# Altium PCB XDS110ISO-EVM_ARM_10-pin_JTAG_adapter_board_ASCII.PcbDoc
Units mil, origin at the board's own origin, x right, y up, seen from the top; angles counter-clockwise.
Board outline 1100 x 500 mil, 2 copper layers (Top Signal, Bottom Signal), stack 58.8 mil thick; 2 components, 6 nets, 25 pads, 15 vias.
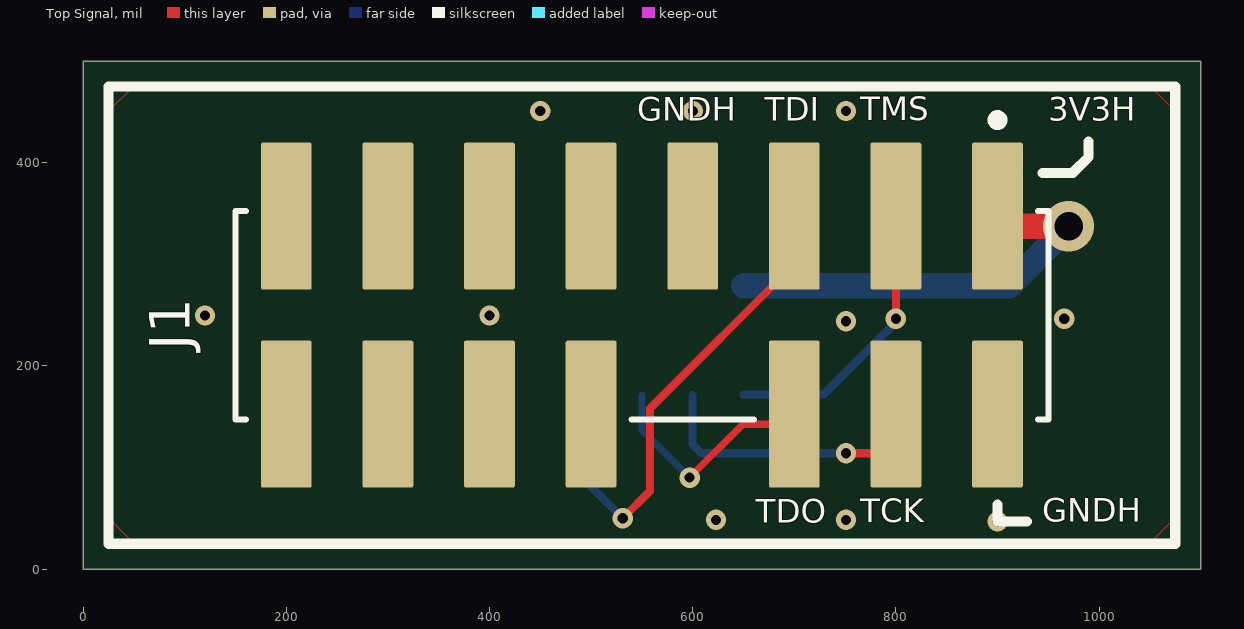
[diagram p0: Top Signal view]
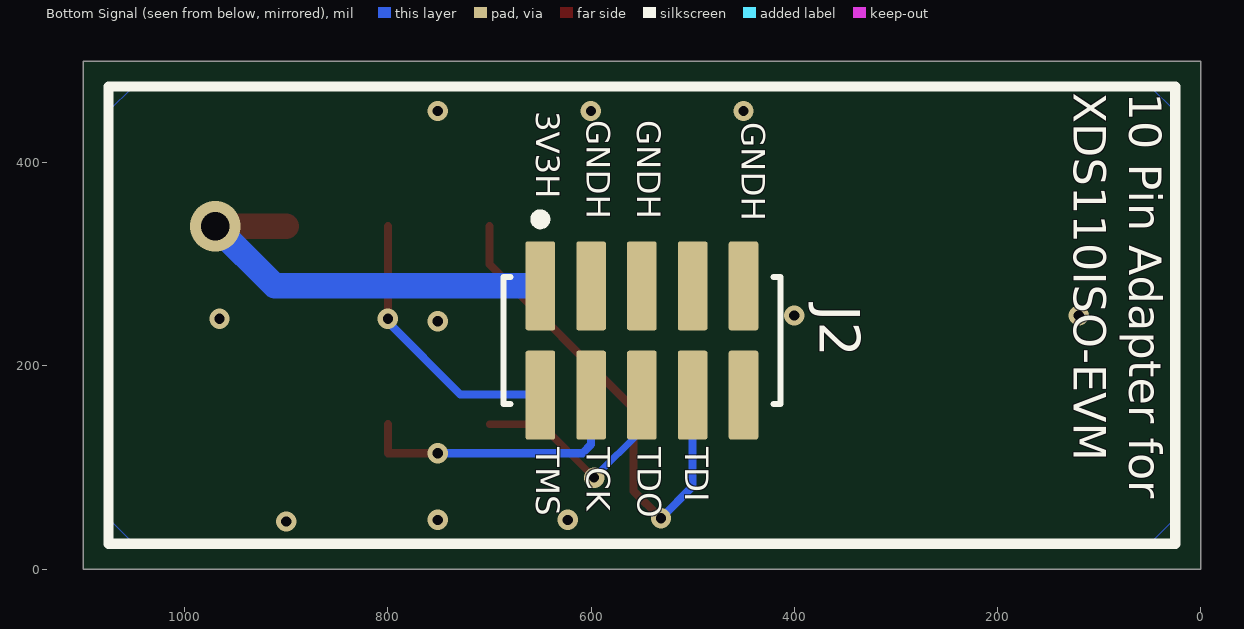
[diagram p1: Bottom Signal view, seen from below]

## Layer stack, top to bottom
Top Solder: solder mask 0.4, Solder Resist, Dk 3.5
Top Signal: signal copper 1.4
Dielectric 1: prepreg 8, FR-4, Dk 4.2
Dielectric 2: core 40, FR-4, Dk 4.2
Dielectric 3: prepreg 8, FR-4, Dk 4.2
Bottom Signal: signal copper 1.4
Bottom Solder: solder mask 0.4, Solder Resist, Dk 3.5

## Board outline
0,0 0,500 1100,500 1100,0

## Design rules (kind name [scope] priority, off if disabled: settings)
AcuteAngle [All] p0: scope1count=1 scope1_0_kind=Board scope1_0_value=Board scope2count=1 scope2_0_kind=Board scope2_0_value=Board commentlength=0 minimum=4.50000000000000E+0001
AcuteAngle [All] p1: minimum=4.50000000000000E+0001 checktracksonly=TRUE
AssemblyTestPointUsage [All] p0: scope1count=1 scope1_0_kind=Board scope1_0_value=Board scope2count=1 scope2_0_kind=Board scope2_0_value=Board commentlength=0
AssemblyTestPointUsage [All] p1: valid=2
AssemblyTestpoint [All] p0: scope1count=1 scope1_0_kind=Board scope1_0_value=Board scope2count=1 scope2_0_kind=Board scope2_0_value=Board commentlength=0
BoardOutlineClearance BoardOutlineClearance_USB101 [All] p0: scope1count=1 scope1_0_kind=Component scope1_0_value=USB101 scope2count=1 scope2_0_kind=Board scope2_0_value=Board commentlength=0 gap=0
BoardOutlineClearance [All] p0 off: scope1count=1 scope1_0_kind=Board scope1_0_value=Board scope2count=1 scope2_0_kind=Board scope2_0_value=Board commentlength=172 gap=10 // Protel DXP Scope 1 Expression Was: OnCopper and Not InComponentClass('Logo') and not InComponentClass('FiducialMark') and not InRegion(1000,500,4000,800) and not InPoly
BoardOutlineClearance BoardOutlineClearance_Poly [All] p0 off: scope1count=1 scope1_0_kind=Board scope1_0_value=Board scope2count=1 scope2_0_kind=Board scope2_0_value=Board commentlength=58 gap=25 // Protel DXP Scope 1 Expression Was: OnCopper and IsPoly
BoardOutlineClearance BoardOutlineClearance_MountingHoles [All] p0 off: scope1count=1 scope1_0_kind=Board scope1_0_value=Board scope2count=1 scope2_0_kind=Board scope2_0_value=Board commentlength=86 gap=40 // Protel DXP Scope 1 Expression Was: OnCopper and InComponentClass('Mounting Holes')
BoardOutlineClearance BoardOutlineClearance_MountingHoles [OnCopper and InComponentClass('Mounting Holes')] p1: gap=40 ignorepadtopadclearanceinfootprint=FALSE
BoardOutlineClearance BoardOutlineClearance_Poly [OnCopper and IsPoly] p2: gap=25 ignorepadtopadclearanceinfootprint=FALSE
BoardOutlineClearance BoardOutlineClearance_USB101 [InComponent('USB101')] p3: gap=0 ignorepadtopadclearanceinfootprint=FALSE
BoardOutlineClearance [OnCopper and Not InComponentClass('Logo') and not InComponentClass('FiducialMark') and not InRegion(1000,500,4000,800) and not InPoly] p4: gap=10 ignorepadtopadclearanceinfootprint=FALSE
Clearance Clearance_PTH [All] p0 off: scope1count=1 scope1_0_kind=Board scope1_0_value=Board scope2count=1 scope2_0_kind=Board scope2_0_value=Board commentlength=56 gap=7 // Protel DXP Scope 1 Expression Was: HoleDiameter > 10
Clearance Clearance_NPTH [All] p0 off: scope1count=1 scope1_0_kind=Board scope1_0_value=Board scope2count=1 scope2_0_kind=Board scope2_0_value=Board commentlength=56 gap=15 // Protel DXP Scope 1 Expression Was: HoleDiameter = 39
Clearance Clearance_FiducialMark [All] p0: scope1count=1 scope1_0_kind=ComponentClass scope1_0_value=FiducialMark scope2count=1 scope2_0_kind=ComponentClass scope2_0_value=FiducialMark commentlength=0 gap=0
Clearance Clearance_Boardedge [All] p0 off: scope1count=1 scope1_0_kind=Board scope1_0_value=Board scope2count=1 scope2_0_kind=Board scope2_0_value=Board commentlength=48 gap=11.8 // Protel DXP Scope 2 Expression Was: IsKeepOut
Clearance [All] p0: scope1count=1 scope1_0_kind=Board scope1_0_value=Board scope2count=1 scope2_0_kind=Board scope2_0_value=Board commentlength=0 gap=6
Clearance Clearance_NPTH [HoleDiameter = 39] p1: gap=15 ignorepadtopadclearanceinfootprint=FALSE
Clearance Clearance_PTH [HoleDiameter > 10] p2: gap=7 ignorepadtopadclearanceinfootprint=FALSE
Clearance Clearance_FiducialMark [InComponentClass('FiducialMark') vs InComponentClass('FiducialMark')] p3: gap=0 ignorepadtopadclearanceinfootprint=FALSE
Clearance Clearance_Boardedge [All vs IsKeepOut] p4: gap=11.8 ignorepadtopadclearanceinfootprint=FALSE
Clearance [All] p5: gap=6 ignorepadtopadclearanceinfootprint=FALSE
ComponentClearance ComponentClearance_THtoTH [All] p0 off: scope1count=1 scope1_0_kind=Board scope1_0_value=Board scope2count=1 scope2_0_kind=Board scope2_0_value=Board commentlength=54 gap=20 collisioncheckmode=3 // Protel DXP Scope 2 Expression Was: IsThruComponent
ComponentClearance ComponentClearance_THtoSMT [All] p0 off: scope1count=1 scope1_0_kind=Board scope1_0_value=Board scope2count=1 scope2_0_kind=Board scope2_0_value=Board commentlength=53 gap=10 collisioncheckmode=3 // Protel DXP Scope 2 Expression Was: IsSMTComponent
ComponentClearance ComponentClearance_SmallPassives [All] p0 off: scope1count=1 scope1_0_kind=Board scope1_0_value=Board scope2count=1 scope2_0_kind=Board scope2_0_value=Board commentlength=508 gap=10 collisioncheckmode=3 // Protel DXP Scope 2 Expression Was: HasFootprint('0201*') or HasFootprint('0402*') or HasFootprint('0508') or HasFootprint('0603*') or HasFootprint('0612') or HasFootprint('0805*') or HasFootprint('0815*') or HasFootprint('0830*') or HasFootprint('1206*') or HasFootprint('1210*') or HasFootprint('1808*') or HasFootprint('1812*') or HasFootprint('1825*') or HasFootprint('2010*') or HasFootprint('2220*') or HasFootprint('2225*') or HasFootprint('2512*') or HasFootprint('2728*') or HasFootprint('3518*')
ComponentClearance ComponentClearance_MountingHoles [All] p0 off: scope1count=1 scope1_0_kind=ComponentClass scope1_0_value="Mounting Holes" scope2count=1 scope2_0_kind=Board scope2_0_value=Board commentlength=0 gap=250 collisioncheckmode=3
ComponentClearance ComponentClearance_ScrewToNut [All] p0 off: scope1count=1 scope1_0_kind=Board scope1_0_value=Board scope2count=1 scope2_0_kind=Board scope2_0_value=Board commentlength=71 gap=3.94 collisioncheckmode=3 // Protel DXP Scope 2 Expression Was: (HasFootprint('Keystone_1902C'))
ComponentClearance ComponentClearance_Logo [All] p0: scope1count=1 scope1_0_kind=ComponentClass scope1_0_value=Logo scope2count=1 scope2_0_kind=Board scope2_0_value=Board commentlength=0 gap=0 collisioncheckmode=3
ComponentClearance ComponentClearance_Shunt [All] p0: scope1count=1 scope1_0_kind=ComponentClass scope1_0_value=Header scope2count=1 scope2_0_kind=ComponentClass scope2_0_value=Shunt commentlength=0 gap=0 collisioncheckmode=3
ComponentClearance ComponentClearance_MountingHoles_FiducialMarks [All] p0: scope1count=1 scope1_0_kind=ComponentClass scope1_0_value="Mounting Holes" scope2count=1 scope2_0_kind=ComponentClass scope2_0_value=FiducialMark commentlength=0 gap=50 collisioncheckmode=3
ComponentClearance ComponentClearance_Logo_1 [All] p0: scope1count=1 scope1_0_kind=ComponentClass scope1_0_value=Logo scope2count=1 scope2_0_kind=ComponentClass scope2_0_value=Logo commentlength=0 gap=0 collisioncheckmode=3
ComponentClearance "ComponentClearance_overlay to overlay" [All] p0 off: scope1count=1 scope1_0_kind=Board scope1_0_value=Board scope2count=1 scope2_0_kind=Board scope2_0_value=Board commentlength=54 gap=0 collisioncheckmode=3 // Protel DXP Scope 2 Expression Was: OnTopSilkscreen
ComponentClearance "ComponentClearance_overlay to overlay" [OnBottomSilkscreen vs OnTopSilkscreen] p1: gap=0 collisioncheckmode=3 verticalgap=0 showdistances=FALSE
ComponentClearance ComponentClearance_MountingHoles_FiducialMarks [InComponentClass('Mounting Holes') vs InComponentClass('FiducialMark')] p2: gap=50 collisioncheckmode=3 verticalgap=10 showdistances=FALSE
ComponentClearance ComponentClearance_Shunt [InComponentClass('Header') vs InComponentClass('Shunt')] p3: gap=0 collisioncheckmode=3 verticalgap=0 showdistances=FALSE
ComponentClearance ComponentClearance_Logo [InComponentClass('Logo')] p4: gap=0 collisioncheckmode=3 verticalgap=0 showdistances=FALSE
ComponentClearance ComponentClearance_Logo_1 [InComponentClass('Logo') vs InComponentClass('Logo')] p5: gap=0 collisioncheckmode=3 verticalgap=0 showdistances=FALSE
ComponentClearance ComponentClearance_ScrewToNut [(HasFootprint('NY PMS 440 0025 PH')) vs (HasFootprint('Keystone_1902C'))] p6: gap=3.94 collisioncheckmode=3 verticalgap=3.94 showdistances=FALSE
ComponentClearance ComponentClearance_MountingHoles [InComponentClass('Mounting Holes')] p7 off: gap=250 collisioncheckmode=3 verticalgap=100000 showdistances=FALSE
ComponentClearance ComponentClearance_SmallPassives [HasFootprint('0201*') or HasFootprint('0402*') or HasFootprint('0508') or HasFootprint('0603*') or HasFootprint('0612') or HasFootprint('0805*') or HasFootprint('0815*') or HasFootprint('0830*') or HasFootprint('1206*') or HasFootprint('1210*') or HasFootprint('1808*') or HasFootprint('1812*') or HasFootprint('1825*') or HasFootprint('2010*') or HasFootprint('2220*') or HasFootprint('2225*') or HasFootprint('2512*') or HasFootprint('2728*') or HasFootprint('3518*') vs HasFootprint('0201*') or HasFootprint('0402*') or HasFootprint('0508') or HasFootprint('0603*') or HasFootprint('0612') or HasFootprint('0805*') or HasFootprint('0815*') or HasFootprint('0830*') or HasFootprint('1206*') or HasFootprint('1210*') or HasFootprint('1808*') or HasFootprint('1812*') or HasFootprint('1825*') or HasFootprint('2010*') or HasFootprint('2220*') or HasFootprint('2225*') or HasFootprint('2512*') or HasFootprint('2728*') or HasFootprint('3518*')] p8 off: gap=10 collisioncheckmode=3 verticalgap=0 showdistances=FALSE
ComponentClearance ComponentClearance_THtoSMT [IsThruComponent vs IsSMTComponent] p9 off: gap=10 collisioncheckmode=3 verticalgap=10 showdistances=FALSE
ComponentClearance ComponentClearance_THtoTH [IsThruComponent vs IsThruComponent] p10 off: gap=20 collisioncheckmode=3 verticalgap=30 showdistances=FALSE
DiffPairsRouting [All] p0: scope1count=1 scope1_0_kind=Board scope1_0_value=Board scope2count=1 scope2_0_kind=Board scope2_0_value=Board commentlength=0
DiffPairsRouting [All] p1: maxlimit=100 minlimit=6 mostfreqgap=6 toplayer_minwidth=5.91 toplayer_maxwidth=15 toplayer_prefwidth=10.63 bottomlayer_minwidth=5.91 bottomlayer_maxwidth=15 bottomlayer_prefwidth=10.63 maxuncoupledlength=1000
FabricationTestPointUsage TestPointUsage [All] p0: scope1count=1 scope1_0_kind=Board scope1_0_value=Board scope2count=1 scope2_0_kind=Board scope2_0_value=Board commentlength=0 valid=2 allowmultiple=FALSE
FabricationTestPointUsage TestPointUsage [All] p1: valid=2 allowmultiple=FALSE
FabricationTestpoint Testpoint [All] p0: scope1count=1 scope1_0_kind=Board scope1_0_value=Board scope2count=1 scope2_0_kind=Board scope2_0_value=Board commentlength=0 side=3 testpointundercomponent=TRUE minsize=40 maxsize=100 preferedsize=60 minholesize=0 maxholesize=40 preferedholesize=32 testpointgrid=1
FabricationTestpoint Testpoint [All] p1: side=3 testpointundercomponent=TRUE minsize=40 maxsize=100 preferedsize=60 minholesize=0 maxholesize=40 preferedholesize=32 testpointgrid=1 allowsidetop=TRUE allowsidebottom=TRUE usegrid=TRUE gridtolerance=0.01
FanoutControl Fanout_Small [All] p0 off: scope1count=1 scope1_0_kind=Board scope1_0_value=Board scope2count=1 scope2_0_kind=Board scope2_0_value=Board commentlength=84 // Protel DXP Scope 1 Expression Was: (CompPinCount < 5)   Fanout_Small (Default Rule)
FanoutControl Fanout_Default [All] p0: scope1count=1 scope1_0_kind=Board scope1_0_value=Board scope2count=1 scope2_0_kind=Board scope2_0_value=Board commentlength=30 // Fanout_Default (Default Rule)
FanoutControl Fanout_SOIC [All] p0 off: scope1count=1 scope1_0_kind=Board scope1_0_value=Board scope2count=1 scope2_0_kind=Board scope2_0_value=Board commentlength=71 // Protel DXP Scope 1 Expression Was: IsSOIC   Fanout_SOIC (Default Rule)
FanoutControl Fanout_BGA [All] p0 off: scope1count=1 scope1_0_kind=Board scope1_0_value=Board scope2count=1 scope2_0_kind=Board scope2_0_value=Board commentlength=69 // Protel DXP Scope 1 Expression Was: IsBGA   Fanout_BGA (Default Rule)
FanoutControl Fanout_LCC [All] p0 off: scope1count=1 scope1_0_kind=Board scope1_0_value=Board scope2count=1 scope2_0_kind=Board scope2_0_value=Board commentlength=69 // Protel DXP Scope 1 Expression Was: IsLCC   Fanout_LCC (Default Rule)
FanoutControl Fanout_LCC [IsLCC] p1: bgadir=Out bgaviamode=Centered fanoutstyle=Auto fanoutdirection=Alternating viagrid=1 // Fanout_LCC (Default Rule)
FanoutControl Fanout_BGA [IsBGA] p2: bgadir=Out bgaviamode=Centered fanoutstyle=Auto fanoutdirection=Alternating viagrid=1 // Fanout_BGA (Default Rule)
FanoutControl Fanout_Default [All] p4: bgadir=Out bgaviamode=Centered fanoutstyle=Auto fanoutdirection=Alternating viagrid=1 // Fanout_Default (Default Rule)
FanoutControl Fanout_Small [(CompPinCount < 5)] p5: bgadir=Out bgaviamode=Centered fanoutstyle=Auto fanoutdirection=OutThenIn viagrid=1 // Fanout_Small (Default Rule)
Height [All] p0: scope1count=1 scope1_0_kind=Board scope1_0_value=Board scope2count=1 scope2_0_kind=Board scope2_0_value=Board commentlength=0
HoleSize [All] p0: scope1count=1 scope1_0_kind=Board scope1_0_value=Board scope2count=1 scope2_0_kind=Board scope2_0_value=Board commentlength=0 absolutevalues=TRUE maxlimit=251 minlimit=7.87 maxpercent=80.000 minpercent=20.000
HoleSize [All] p1: absolutevalues=TRUE maxlimit=251 minlimit=7.87 maxpercent=80.000 minpercent=20.000
HoleToHoleClearance HoleToHoleClearance_USB101 [All] p0: scope1count=1 scope1_0_kind=Component scope1_0_value=USB101 scope2count=1 scope2_0_kind=Component scope2_0_value=USB101 commentlength=0
HoleToHoleClearance [All] p0: scope1count=1 scope1_0_kind=Board scope1_0_value=Board scope2count=1 scope2_0_kind=Board scope2_0_value=Board commentlength=0
HoleToHoleClearance HoleToHoleClearance_USB101 [InComponent('USB101') vs InComponent('USB101')] p1: gap=0 allowstackedmicrovias=TRUE
HoleToHoleClearance [All] p2: gap=12 allowstackedmicrovias=TRUE
LayerPairs [All] p0: scope1count=1 scope1_0_kind=Board scope1_0_value=Board scope2count=1 scope2_0_kind=Board scope2_0_value=Board commentlength=0 enforce=TRUE
MatchedLengths FSIRX [All] p0: scope1count=1 scope1_0_kind=NetClass scope1_0_value=FSIRX scope2count=1 scope2_0_kind=Board scope2_0_value=Board commentlength=0 tolerance=25 amplitude=200 gap=20 style=90-Degree
MatchedLengths FSITX [All] p0: scope1count=1 scope1_0_kind=NetClass scope1_0_value=FSITX scope2count=1 scope2_0_kind=Board scope2_0_value=Board commentlength=0 tolerance=25 amplitude=200 gap=20 style=90-Degree
MatchedLengths FSIRX [InNetClass('FSIRX')] p1: tolerance=25 checknetsindiffpair=FALSE checkdiffpairvsdiffpair=TRUE checkxsignals=TRUE checkothers=TRUE
MatchedLengths FSITX [InNetClass('FSITX')] p2: tolerance=25 checknetsindiffpair=FALSE checkdiffpairvsdiffpair=TRUE checkxsignals=TRUE checkothers=TRUE
MinimumAnnularRing [All] p0: scope1count=1 scope1_0_kind=Board scope1_0_value=Board scope2count=1 scope2_0_kind=Board scope2_0_value=Board commentlength=0 minimumring=5
MinimumAnnularRing MinimumAnnularRing_ThermalPadVias [All] p0 off: scope1count=1 scope1_0_kind=Board scope1_0_value=Board scope2count=1 scope2_0_kind=Board scope2_0_value=Board commentlength=63 minimumring=5 // Protel DXP Scope 1 Expression Was: IsVia and InAnyComponent
MinimumAnnularRing MinimumAnnularRing_ThermalPadVias [IsVia and InAnyComponent] p1: minimumring=5
MinimumAnnularRing [All] p2: minimumring=5
MinimumSolderMaskSliver [All] p0: scope1count=1 scope1_0_kind=Board scope1_0_value=Board scope2count=1 scope2_0_kind=Board scope2_0_value=Board commentlength=0
MinimumSolderMaskSliver MinimumSolderMaskSliver_Logo [All] p0: scope1count=1 scope1_0_kind=ComponentClass scope1_0_value=Logo scope2count=1 scope2_0_kind=ComponentClass scope2_0_value=Logo commentlength=0
MinimumSolderMaskSliver MinimumSolderMaskSliver_Logo [InComponentClass('Logo') vs InComponentClass('Logo')] p1: minsoldermaskwidth=0.7
MinimumSolderMaskSliver [All] p2: minsoldermaskwidth=0
NetAntennae [All] p0: scope1count=1 scope1_0_kind=Board scope1_0_value=Board scope2count=1 scope2_0_kind=Board scope2_0_value=Board commentlength=0
PasteMaskExpansion [All] p0: scope1count=1 scope1_0_kind=Board scope1_0_value=Board scope2count=1 scope2_0_kind=Board scope2_0_value=Board commentlength=0 expansion=0
PlaneClearance [All] p0: scope1count=1 scope1_0_kind=Board scope1_0_value=Board scope2count=1 scope2_0_kind=Board scope2_0_value=Board commentlength=0 clearance=6
PlaneClearance [All] p1: clearance=6
PlaneConnect [All] p0: scope1count=1 scope1_0_kind=Board scope1_0_value=Board scope2count=1 scope2_0_kind=Board scope2_0_value=Board commentlength=0 planeconnectstyle=Relief reliefexpansion=7 reliefentries=4 reliefconductorwidth=8 reliefairgap=6
PlaneConnect [All] p1: planeconnectstyle=Relief reliefexpansion=7 reliefentries=4 reliefconductorwidth=8 reliefairgap=6
PolygonConnect PolygonConnect_GNDH [All] p0 off: scope1count=1 scope1_0_kind=Board scope1_0_value=Board scope2count=1 scope2_0_kind=Board scope2_0_value=Board commentlength=70 connectstyle=Relief reliefconductorwidth=30 reliefentries=4 polygonreliefangle="90 Angle" // Protel DXP Scope 1 Expression Was: InNet('+3V3H') OR InNet('GNDH')
PolygonConnect PolygonConnect_via [All] p0 off: scope1count=1 scope1_0_kind=Board scope1_0_value=Board scope2count=1 scope2_0_kind=Board scope2_0_value=Board commentlength=44 connectstyle=Relief reliefconductorwidth=8 reliefentries=4 polygonreliefangle="90 Angle" // Protel DXP Scope 1 Expression Was: isvia
PolygonConnect [All] p0: scope1count=1 scope1_0_kind=Board scope1_0_value=Board scope2count=1 scope2_0_kind=Board scope2_0_value=Board commentlength=0 connectstyle=Relief reliefconductorwidth=8 reliefentries=4 polygonreliefangle="90 Angle"
PolygonConnect PolygonConnect_GNDH [InNet('+3V3H') OR InNet('GNDH')] p1: connectstyle=Relief reliefconductorwidth=30 reliefentries=4 polygonreliefangle="90 Angle" airgapwidth=6
PolygonConnect PolygonConnect_via [isvia] p2: connectstyle=Relief reliefconductorwidth=8 reliefentries=4 polygonreliefangle="90 Angle" airgapwidth=6
PolygonConnect [All] p3: connectstyle=Relief reliefconductorwidth=8 reliefentries=4 polygonreliefangle="90 Angle" airgapwidth=6
RoutingCorners [All] p0: scope1count=1 scope1_0_kind=Board scope1_0_value=Board scope2count=1 scope2_0_kind=Board scope2_0_value=Board commentlength=0 cornerstyle=45-Degree minsetback=100 maxsetback=100
RoutingLayers [All] p0: scope1count=1 scope1_0_kind=Board scope1_0_value=Board scope2count=1 scope2_0_kind=Board scope2_0_value=Board commentlength=0 top layer=Automatic bottom layer=Automatic
RoutingPriority [All] p0: scope1count=1 scope1_0_kind=Board scope1_0_value=Board scope2count=1 scope2_0_kind=Board scope2_0_value=Board commentlength=0
RoutingTopology [All] p0: scope1count=1 scope1_0_kind=Board scope1_0_value=Board scope2count=1 scope2_0_kind=Board scope2_0_value=Board commentlength=0 topology=Shortest
RoutingVias RoutingVias_PWR [All] p0: scope1count=1 scope1_0_kind=Net scope1_0_value=+3V3H scope2count=1 scope2_0_kind=Board scope2_0_value=Board commentlength=0 holewidth=28 width=50 viastyle="Through Hole" minholewidth=28 minwidth=50 maxholewidth=28 maxwidth=50
RoutingVias [All] p0: scope1count=1 scope1_0_kind=Board scope1_0_value=Board scope2count=1 scope2_0_kind=Board scope2_0_value=Board commentlength=0 holewidth=10 width=20 viastyle="Through Hole" minholewidth=10 minwidth=20 maxholewidth=20 maxwidth=40
RoutingVias ThermalPadVias [All] p0: scope1count=1 scope1_0_kind=Board scope1_0_value=Board scope2count=1 scope2_0_kind=Board scope2_0_value=Board commentlength=0 holewidth=10 width=20 viastyle="Through Hole" minholewidth=10 minwidth=20 maxholewidth=20 maxwidth=40
RoutingVias RoutingVias_PWR [InNet('+3V3H')] p1: holewidth=28 width=50 viastyle="Through Hole" minholewidth=28 minwidth=50 maxholewidth=28 maxwidth=50
RoutingVias ThermalPadVias [All] p2: holewidth=10 width=20 viastyle="Through Hole" minholewidth=10 minwidth=20 maxholewidth=20 maxwidth=40
RoutingVias [All] p3: holewidth=10 width=20 viastyle="Through Hole" minholewidth=10 minwidth=20 maxholewidth=20 maxwidth=40
ShortCircuit [All] p0: scope1count=1 scope1_0_kind=Board scope1_0_value=Board scope2count=1 scope2_0_kind=Board scope2_0_value=Board commentlength=0 allowed=FALSE
SilkToBoardRegionClearance [All] p0 off: scope1count=1 scope1_0_kind=Board scope1_0_value=Board scope2count=1 scope2_0_kind=Board scope2_0_value=Board commentlength=130 // Protel DXP Scope 1 Expression Was: Not ((IsComment or IsDesignator) And (Hide <> 'False')) and not InRegion(1000,500,4000,800)
SilkToBoardRegionClearance [Not ((IsComment or IsDesignator) And (Hide <> 'False')) and not InRegion(1000,500,4000,800)] p1:
SilkToSilkClearance [All] p0: scope1count=1 scope1_0_kind=Board scope1_0_value=Board scope2count=1 scope2_0_kind=Board scope2_0_value=Board commentlength=0
SilkToSilkClearance SilkToSilkClearance_Pb-FreeLogo [All] p0 off: scope1count=1 scope1_0_kind=Board scope1_0_value=Board scope2count=1 scope2_0_kind=Board scope2_0_value=Board commentlength=120 // Protel DXP Scope 2 Expression Was: (HasFootprint('Pb-Free_Overlay_Medium') OR HasFootprint('Pb-Free_Overlay_Small'))
SilkToSilkClearance SilkToSilkClearance_Pb-FreeLogo [(HasFootprint('Pb-Free_Overlay_Medium') OR HasFootprint('Pb-Free_Overlay_Small')) vs (HasFootprint('Pb-Free_Overlay_Medium') OR HasFootprint('Pb-Free_Overlay_Small'))] p1: silktosilkclearance=0
SilkToSilkClearance [All] p2: silktosilkclearance=3
SilkToSolderMaskClearance "Silk to Solder Mask Opening" [All] p0: scope1count=1 scope1_0_kind=Board scope1_0_value=Board scope2count=1 scope2_0_kind=Board scope2_0_value=Board commentlength=0
SilkToSolderMaskClearance SilkToComponentPadClearance [All] p0 off: scope1count=1 scope1_0_kind=Board scope1_0_value=Board scope2count=1 scope2_0_kind=Board scope2_0_value=Board commentlength=87 // Protel DXP Scope 1 Expression Was: (IsPad or IsFill or IsRegion) and InAnycomponent
SilkToSolderMaskClearance SilkToComponentPadClearance [(IsPad or IsFill or IsRegion) and InAnycomponent] p1: minsilkscreentomaskgap=2.5 clearancetoexposedcopper=TRUE
SilkToSolderMaskClearance "Silk to Solder Mask Opening" [All] p2: minsilkscreentomaskgap=2.5 clearancetoexposedcopper=TRUE
SolderMaskExpansion [All] p0: scope1count=1 scope1_0_kind=Board scope1_0_value=Board scope2count=1 scope2_0_kind=Board scope2_0_value=Board commentlength=0 expansion=2
SolderMaskExpansion [All] p1: expansion=2 istentingtop=FALSE
UnRoutedNet [All] p0: scope1count=1 scope1_0_kind=Board scope1_0_value=Board scope2count=1 scope2_0_kind=Board scope2_0_value=Board commentlength=0
UnRoutedNet [All] p1: checkbadconnections=TRUE
UnpouredPolygon [All] p0: scope1count=1 scope1_0_kind=Board scope1_0_value=Board scope2count=1 scope2_0_kind=Board scope2_0_value=Board commentlength=0
Width [All] p0: scope1count=1 scope1_0_kind=Board scope1_0_value=Board scope2count=1 scope2_0_kind=Board scope2_0_value=Board commentlength=0 maxlimit=100 minlimit=7 preferedwidth=8
Width Analog [All] p0: scope1count=1 scope1_0_kind=NetClass scope1_0_value=Analog scope2count=1 scope2_0_kind=Board scope2_0_value=Board commentlength=0 maxlimit=25 minlimit=8 preferedwidth=8
Width Analog [InNetClass('Analog')] p1: maxlimit=25 minlimit=8 preferedwidth=8
Width [All] p2: maxlimit=100 minlimit=7 preferedwidth=8 minimp=50.000000 maximp=50.000000 favimp=50.000000 checkconnectedcopper=TRUE
12 further rules are at their usual default settings.

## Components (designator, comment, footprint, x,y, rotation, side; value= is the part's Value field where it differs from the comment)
J1 "TSM-108-01-L-DV-008-P-TR" FP-TSM-108-01-L-DV-008-P-TR_HDR15-MFG 550,250 r180 top
J2 "SFMC-105-02-S-D-K-TR" FP-SFMC-105-02-S-D-K-TR_CONN_RCPT10-MFG 550,225 r0 bottom

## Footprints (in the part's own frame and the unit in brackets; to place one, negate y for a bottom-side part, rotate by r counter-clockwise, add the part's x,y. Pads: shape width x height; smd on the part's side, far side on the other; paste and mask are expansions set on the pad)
FP-SFMC-105-02-S-D-K-TR_CONN_RCPT10-MFG [mm]
  rrect14% 0.74x2.22 smd paste+0 mask+0: 1(2.54,-1.365) 2(2.54,1.365) 3(1.27,-1.365) 4(1.27,1.365) 5(0,-1.365) 6(0,1.365) 7(-1.27,-1.365) 8(-1.27,1.365) 9(-2.54,-1.365) 10(-2.54,1.365)
  silkscreen extent -3.47,-3.15 3.47,1.59
FP-TSM-108-01-L-DV-008-P-TR_HDR15-MFG [mm]
  rrect8% 1.27x3.68 smd paste+0 mask+0: 1(-8.89,-2.475) 2(-8.89,2.475) 3(-6.35,-2.475) 4(-6.35,2.475) 5(-3.81,-2.475) 6(-3.81,2.475) 7(-1.27,-2.475) 9(1.27,-2.475) 10(1.27,2.475) 11(3.81,-2.475) 12(3.81,2.475) 13(6.35,-2.475) 14(6.35,2.475) 15(8.89,-2.475) 16(8.89,2.475)
  silkscreen extent -10.16,-5 10.16,2.6

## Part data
J1: library part CMP-0121706-1, "Conn Unshrouded HDR 16 POS 2.54mm Solder ST SMT"
J2: library part CMP-0121829-1, "10 Position Receptacle Connector 0.050\" (1.27mm) Surface Mount Gold"

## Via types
v1: diameter 20, hole 10, Top Signal to Bottom Signal, tented both sides, 14 vias
v2: diameter 50, hole 28, Top Signal to Bottom Signal, tented both sides, 1 vias

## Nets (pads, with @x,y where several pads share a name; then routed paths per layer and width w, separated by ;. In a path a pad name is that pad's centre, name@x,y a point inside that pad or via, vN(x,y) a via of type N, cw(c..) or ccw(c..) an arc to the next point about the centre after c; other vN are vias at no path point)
+3V3H: J1.1 J2.1 | length 414.3
  Top Signal w25: J1.1@900,337.44 v2(970,337.44)
  Bottom Signal w25: J2.1 911.3,278.74 v2(970,337.44)
GNDH: J1.2 J1.7 J2.3 J2.5 J2.9
  other v1: 900,46.82 623.02,48.46 750.98,48.46 750.96,243.98 965.79,246.39 120,249.58 400,249.58 450,450.81 600.18,450.81 750.96,450.81
MCU_TCK: J1.4 J2.4 | length 280.9
  Top Signal w8: v1(750.96,113.99) 800,113.99 J1.4@800,142.56
  Bottom Signal w8: J2.4 600,122.44 608.45,113.99 v1(750.96,113.99)
MCU_TDI: J1.5 J2.8 | length 491.5
  Top Signal w8: v1(531.16,50) 558.15,76.99 558.15,158.15 700,300 J1.5@700,337.44
  Bottom Signal w8: J2.8 500,154.57 500,81.16 v1(531.16,50)
MCU_TDO: J1.6 J2.6 | length 225.5
  Top Signal w7: v1(597,90) 649.56,142.56 J1.6@700,142.56
  Bottom Signal w7: J2.6 550,137 v1(597,90)
MCU_TMS: J1.3 J2.2 | length 274.5
  Top Signal w8: v1(800,246.39) J1.3@800,337.44
  Bottom Signal w8: J2.2 650,171.99 728.77,171.99 800,243.21 v1(800,246.39)
pads on no net: J1.9 J1.10 J1.11 J1.12 J1.13 J1.14 J1.15 J1.16 J2.7 J2.10

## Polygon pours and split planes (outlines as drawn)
GNDH on Bottom Signal "NONET_L-01_P-001" (solid, remove dead copper, pour order 22): 1050,475 50,475 25,450.81 25,50 50,25 1050,25 1075,50 1075,450.81
GNDH on Top Signal "NONET_L-01_P-001" (solid, remove dead copper, pour order 15): 50,475 25,450.81 25,50.49 50,25.49 1050,25.49 1075,50.49 1075.22,450.81 1050,475

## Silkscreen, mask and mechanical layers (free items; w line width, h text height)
Top Overlay:
  lines w10: 900,63.56 900,46.82 928.89,46.82 ; 944.39,390 974.21,390 989.65,405.44 989.65,421 ; 25,25 25,475 1075,475 ; 25,25 1075,25 ; 25,25 1075,25 ; 1075,25 1075,475 ; 1075,25 1075,475
  text "GNDH" at 545.56,433.49 h40
  text "TDI" at 670.72,433.49 h40
  text "TMS" at 765,433.98 h40
  text "3V3H" at 950,433.49 h40
  text "GNDH" at 943.94,38.83 h40
  text "TDO" at 662.24,37.92 h40
  text "TCK" at 765,38.41 h40
Bottom Overlay:
  lines w10: 25,474.51 25,25 1075,25 1075,474.51 ; 25,475 1075,475
  text "10 Pin Adapter for / XDS110ISO-EVM" at 136,468.83 h55 r90
  text "3V3H" at 661.82,450.81 h40 r90
  text "GNDH" at 562.58,441.93 h40 r90
  text "GNDH" at 612.11,441.93 h40 r90
  text "GNDH" at 459.58,440 h40 r90
  text "TDI" at 515,120 h40 r90
  text "TDO" at 562.16,120 h40 r90
  text "TCK" at 612.11,120 h40 r90
  text "TMS" at 661.74,120 h40 r90
M1 Board Outline:
  the board outline again, w10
